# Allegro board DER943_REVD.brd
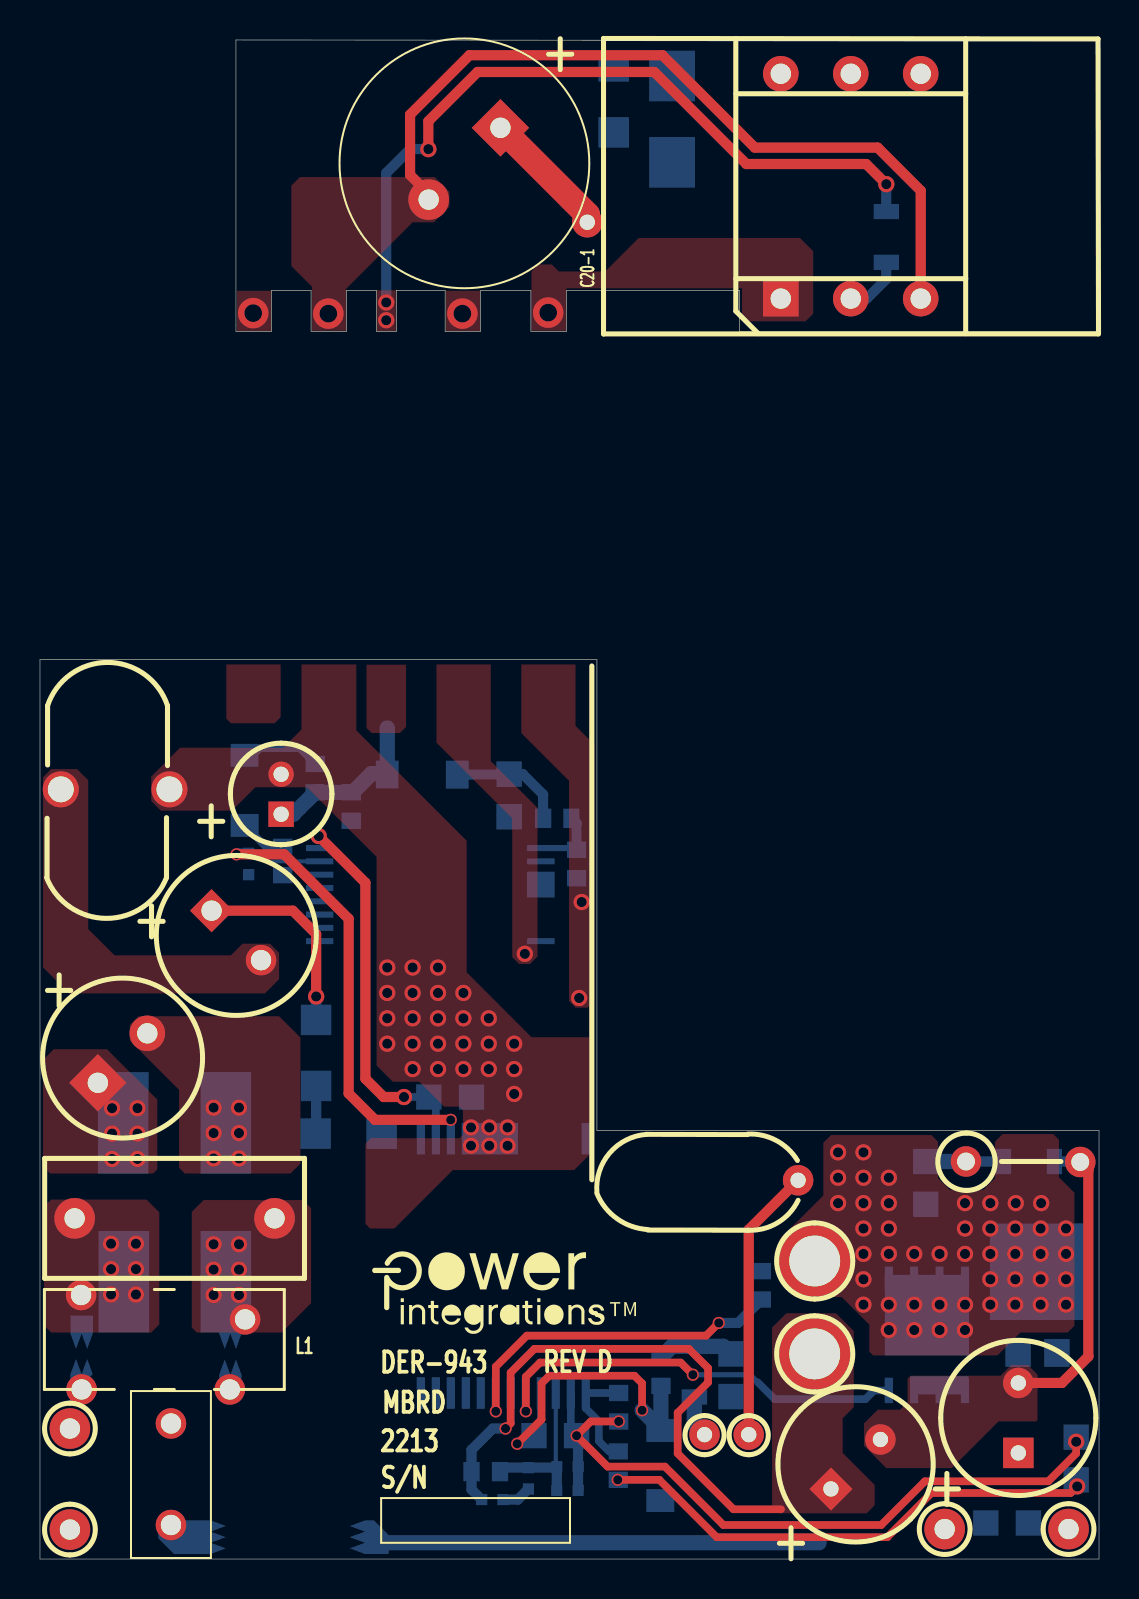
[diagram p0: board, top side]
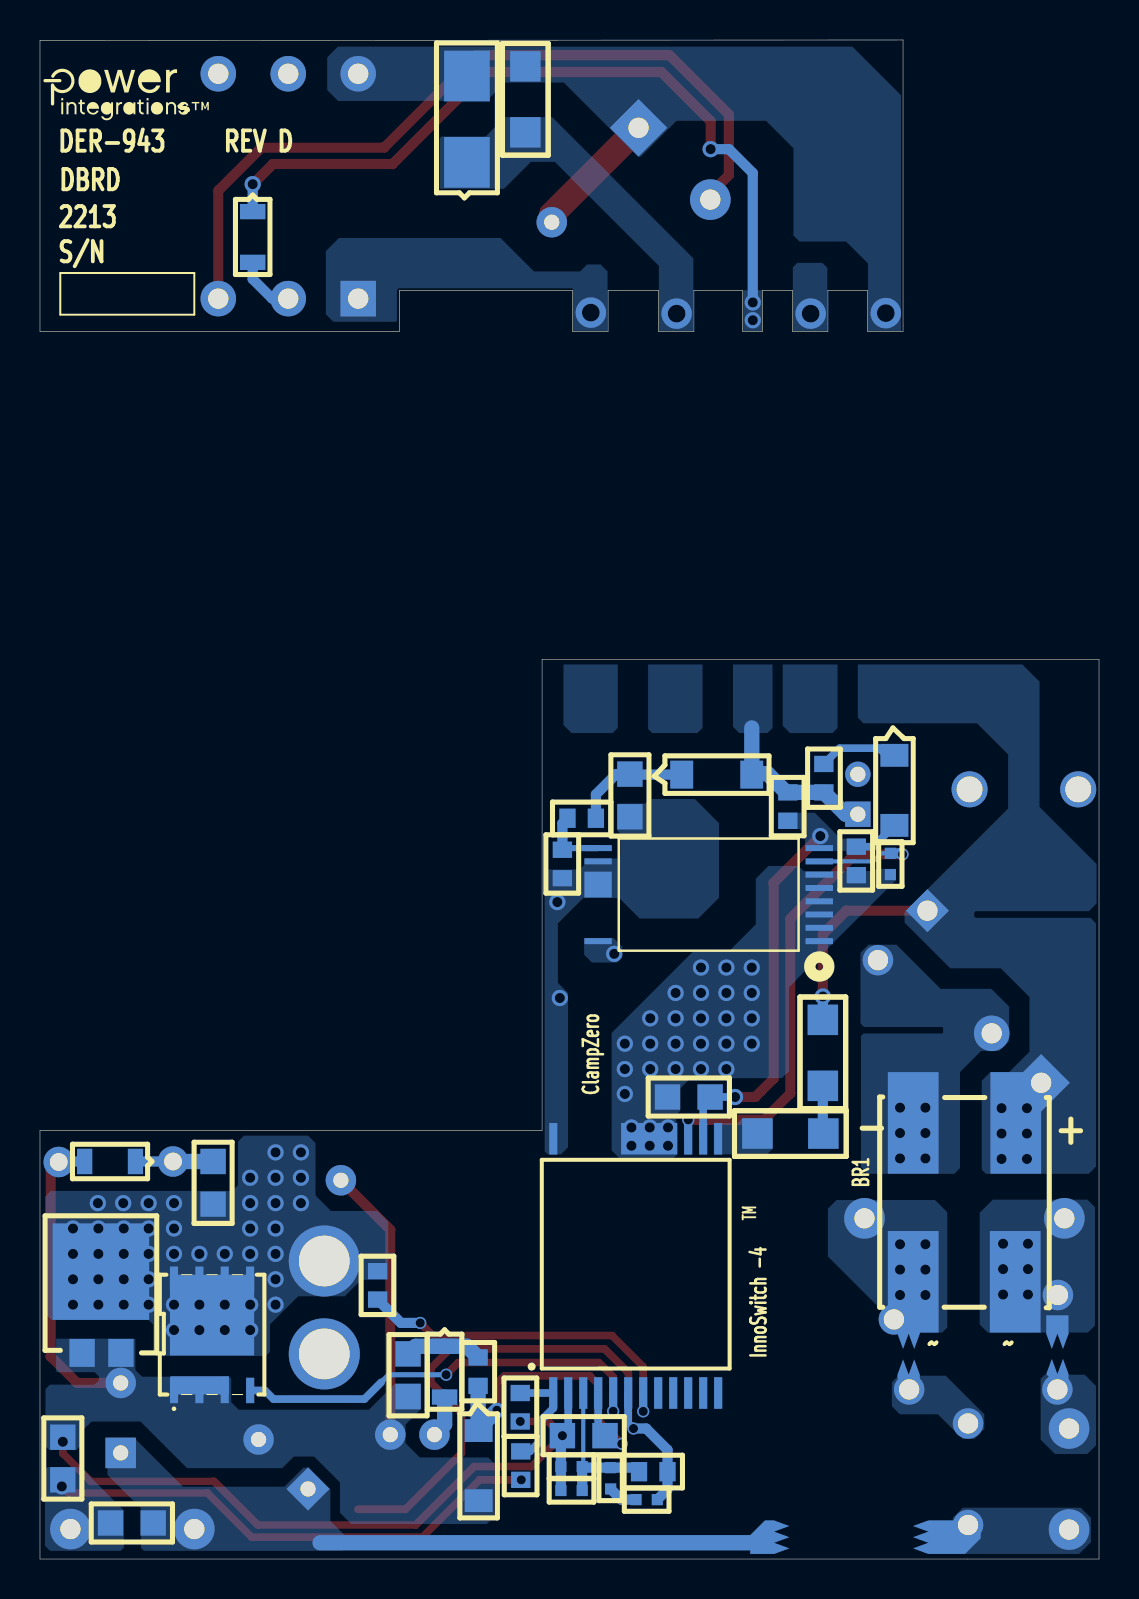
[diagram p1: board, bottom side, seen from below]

Outline 52.98 x 76 mm; copper layers: TOP, BOTTOM. Coordinates in mm from the lower left corner of the outline.
Outline path: 0,45.01 0,0 52.98,0 52.98,21.44 27.86,21.44 27.86,45.01 0,45.01 ; 9.8,76 9.8,61.42 11.58,61.42 11.58,63.47 13.56,63.47 13.56,61.42 15.34,61.42 15.34,63.47 16.84,63.47 16.84,61.42 17.83,61.42 17.83,63.47 20.27,63.47 20.27,61.42 22.05,61.42 22.05,63.47 24.56,63.47 24.56,61.42 26.34,61.42 26.34,63.47 35,63.47 35,61.42 52.98,61.42 52.98,75.97 9.86,76 9.8,76

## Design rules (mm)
constraint set DEFAULT: min track width 0.508

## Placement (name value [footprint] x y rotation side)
BR1  Z4DGP408L-HF  [PI_SM_D_Z4D]  4.19 21.87 180 bottom
C1  0.1 uF  [PINPXCAPRAD13X6X12P1MM040]  11.73 17.04 180 top
C2  10  uF  [PI_POLCAPD8MMXLLS3P5MM063V]  2.9 23.83 45 top
C3  10  uF  [PI_POLCAPD8MMXLLS3P5MM063V]  8.59 32.44 315 top
C4  100 uF  [PIPOLCAPCLYD500LS200040]  23.04 71.6 225 top
C5  100 nF  [PISMC1206]  28.7 74.68 270 bottom
C6  100 nF  [PISMC0603]  26.85 35.48 270 bottom
C7  1 uF  [PISMC0805]  23.47 37.13 90 bottom
C8  100 nF  [PISMC0603]  12.14 35.64 270 bottom
C9  22 uF  [PIPOLCAPCLYD200LS80030]  12.06 37.26 90 top
C10  0.47 uF  [PISMC0805]  19.46 23.11 0 bottom
C11  1 nF  [PISMC0805]  44.32 17.75 90 bottom
C12  330 uF  [PIPOLCAPCYLD315LS138D030]  39.57 3.51 45 top
C13  330 uF  [PIPOLCAPCYLD315LS138D030]  48.95 5.31 90 top
C14  330 pF  [PISMR0402]  24.43 3.51 90 bottom
C15  330 pF  [PISMR0402]  25.86 4.62 0 bottom
C16  1 uF  [PISMC0805]  47.32 1.8 0 bottom
C17  2.2 uF  [PISMC0805]  26.85 6.17 180 bottom
C18  10 uF  [PISMC0805]  34.57 10.26 270 bottom
C19  4.7 uF  [PISMC0603]  28.96 6.88 90 bottom
C20  470 pF  [PINPCAPRAD7P5X11P5LS7P5MM030]  30.43 18.95 0 top
D1  HS1KFL  [PI_SM_SOD-123_12]  20.88 39.24 180 bottom
D2  BAV19WS  [PISMSOD323]  42.34 67.41 270 bottom
D3  V12P10-M3/86A  [PI_SM_D_TO-277A]  48.92 10.31 180 bottom
D4  BAV19WS  [PISMSOD323]  48.21 19.89 0 bottom
D5  BAV19WS  [PISMSOD323]  32.74 10.64 270 bottom
F1  3.15 A  [PI_RST_MICROFUSE]  6.55 1.7 90 top
FL1  Hole_70mils  [PI_HOLE_70MIL]  38.76 10.24 0 top
FL2  Hole_70mils  [PI_HOLE_70MIL]  38.76 14.88 0 top
FL3  Hole_30mils  [PI_HOLE_30MIL]  33.25 6.22 0 top
FL4  Hole_30mils  [PI_HOLE_30MIL]  35.46 6.22 0 top
GND  BLK  [PITPKEYSTONE100X100]  51.46 1.5 0 top
L  BLK  [PITPKEYSTONE100X100]  1.5 1.47 0 top
L1  415 uH  [PI_TOROID_CMC4P_V_275UH]  7.72 8.48 180 top
L2  68 uH  [PI2P14DX6MMWD060]  0.3 38.51 0 top
N  WHT  [PITPKEYSTONE100X100]  1.5 6.53 0 top
NOREF  -  []  0 45.01 0 top
NOREF#2  -  []  0 0 0 top
NOREF#3  -  []  16.64 15.82 0 top
NOREF#4  -  []  35 61.42 0 top
NOREF#5  -  []  9.8 63.47 90 top
NOREF#6  -  []  9.8 76 0 top
NOREF#7  -  []  -144.21 54.23 0 top
NOREF#8  -  []  52.98 0 90 top
NOREF#9  -  []  0 0 90 top
NOREF#10  -  []  -222.02 -144.78 0 top
NOREF#11  -  []  52.98 61.42 90 top
NOREF#12  -  []  53.37 74.45 180 bottom
Q1  AON6220  [PISMPQFN5X6B]  46.28 8.43 180 bottom
R1  1.3 k  [PISMR0603]  26.59 37.06 180 bottom
R2  30 k  [PISMR0402]  10.44 35.31 270 bottom
R3  1.1 k  [PISMR0603]  15.57 38.35 270 bottom
R4  47  [PISMR0603]  13.77 38.35 90 bottom
R5  2.00 M  [PISMR1206]  13.82 26.97 270 bottom
R6  2.00 M  [PISMR1206]  13.79 21.29 0 bottom
R7  300  [PISMR0603]  36.09 14.4 270 bottom
R8  10  [PI12WVRESD180LS150D040]  46.33 19.89 0 top
R9  169 k  [PISMR0603]  21.59 4.37 0 bottom
R10  11.3 k  [PISMR0402]  25.86 3.43 0 bottom
R11  10 K  [PISMR0402]  22.1 2.97 0 bottom
R12  470  [PISMR0603]  31.06 8.66 90 bottom
R13  10  [PISMR0603]  28.93 5.38 270 bottom
R14  0.010  [PISMR0805]  51.84 6.1 270 bottom
T1  ATQ23.7/14  [PI_BOBBIN_ATQ23_7_H_6P]  40.56 68.68 90 top
U1  CPZ1075M  [PI_SM_MINSOP16A_1]  14 30.91 90 bottom
U2  INN4075C-H180  [PI_IC_INSOP_24D_IPC]  27.3 8.31 90 bottom
VOUT  RED  [PITPKEYSTONE100X100]  45.26 1.5 0 top
VR1  SMAJ170A-13-F  [PISMDO214AC12]  31.62 69.88 90 bottom
VR2  MMSZ5239B-7-F  [PI_SM_SOD-123_12]  10.24 40.21 270 bottom
VR3  DNP  [PI_SM_SOD-123_12]  31.04 6.43 270 bottom

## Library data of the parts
BR1 = DISCRETE BRIDGE_+~~-
C1 = CAP NP: alternate symbols: (pinpxcaprad13x6x12p1mm040H)
C2 C3 = CAP POL: alternate symbols: (PI_POLCAPD8mmxlLS3p5mm063V)
C4 = CAP POL: alternate symbols: (pipolcapclyd500ls2000401650lh)
C5-C8 C10 C16-C20 = CAP NP
C9 = CAP POL: alternate symbols: (pipolcapclyd200ls80030h)
C11 = CAP NP: alternate symbols: (pismc0805_1)
C12 C13 = CAP POL: alternate symbols: (pipolcapcyld315ls138d030h)
C14 C15 = CAP NP: alternate symbols: (pismr0402_1)
D1 D2 D4 D5 = DIODE
D3 = DIODE SCHOTTKY_TO-277A
F1 = FUSE: alternate symbols: (pirstmicrofusehoz)
FL1-FL4 = FlyingLead
GND L = TESTPOINT: alternate symbols: (TP_TH_CR2_D1_1)
L1 = TORRID 4P_12_34: alternate symbols: (pi_toroid_CMC4p_V,pi_toroid_CMC4p_V_275uH)
L2 = INDUCTOR
N VOUT = TESTPOINT
Q1 = FET_N_SGD_123_4_5678
R1-R3 R5-R7 R9-R14 = R
R4 = R: alternate symbols: (pismr0603_1)
R8 = R: alternate symbols: (pi12wvresd180ls200d040,pi12wvresd180ls250d040,pi12wresd180ls675d040)
T1 = BATQ23_7_6P/GENERIC
U1 = ClampZeroMinSOP16
U2 = MinnoPriSecCZ: alternate symbols: (pi_ic_insop_24d,PI_IC_INSOP24B)
VR1-VR3 = DIODE_ZENER

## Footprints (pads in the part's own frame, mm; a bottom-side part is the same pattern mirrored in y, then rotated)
PI2P14DX6MMWD060
  round 1.803 hole 1.295: 1(0.737,0) 2(6.172,0)
PI12WVRESD180LS150D040
  round 1.524 hole 0.889: 1(0,0) 2(5.715,-0.025)
PI_BOBBIN_ATQ23_7_H_6P
  rect 1.778x1.778 hole 1.016: 1(-5.625,3.5)
  round 1.778 hole 1.016: 2(-5.625,0) 3(-5.625,-3.5) 4(5.625,-3.5) 5(5.625,0) 6(5.625,3.5)
PI_HOLE_30MIL
  round 1.524 hole 0.762: 1(0,0)
PI_HOLE_70MIL
  round 3.556 hole 2.54: 1(0,0.025)
PI_IC_INSOP_24D_IPC
  rect 1.58x0.409 smd: 1(0,0) 2(0,-0.749) 3(0,-1.501) 4(0,-2.25) 5(0,-3) 6(0,-3.749) 7(0,-4.501) 8(0,-5.25) 9(0,-6) 10(0,-6.749) 11(0,-7.501) 12(0,-8.25) 13(12.72,-8.25) 14(12.72,-7.501) 15(12.72,-6.749) 24(12.72,0)
  rect 1.58x2.809 smd: 16(12.72,-4.801)
PI_POLCAPD8MMXLLS3P5MM063V
  rect 2.032x2.032 hole 1.016: 1(0,0)
  round 1.778 hole 1.016: 2(3.5,0)
PI_RST_MICROFUSE
  round 1.524 hole 1.016: 1(0,0) 2(5.08,0)
PI_SM_D_TO-277A
  rect 1.27x1.397 smd: 1(-0.015,0) 2(-1.956,0)
  rect 4.826x4.826 smd: 3(-1.016,4.064)
PI_SM_D_Z4D
  rect 2.54x5.08 smd: 1(0.025,-0.051) 2(0,-8.001) 3(-5.105,-8.001) 4(-5.105,-0.051)
PI_SM_MINSOP16A_1
  rect 0.3x1.369 smd: 1(0,0) 2(0.666,0) 3(1.331,0) 4(1.994,0) 5(2.659,0) 6(3.325,0) 7(3.99,0) 8(4.656,0) 9(4.656,11.067) 10(3.99,11.067) 16(0,11.067)
  rect 1.293x1.369 smd: 11(2.83,11.067)
PI_SM_SOD-123_12
  rect 1.143x1.397 smd: 1(0,0) 2(3.505,0)
PI_TOROID_CMC4P_V_275UH
  round 1.524 hole 1.016: 1(-1.778,0) 2(-2.54,-3.505) 3(5.639,0) 4(5.664,-4.724)
PINPCAPRAD7P5X11P5LS7P5MM030
  round 1.524 hole 0.762: 1(-3.048,47.93) 2(7.501,0)
PINPXCAPRAD13X6X12P1MM040
  round 2.032 hole 1.016: 1(0,0) 2(10,0)
PIPOLCAPCLYD200LS80030
  rect 1.27x1.27 hole 0.762: 1(0,0)
  round 1.27 hole 0.762: 2(1.999,0)
PIPOLCAPCLYD500LS200040
  rect 2.032x2.032 hole 1.016: 1(0,0)
  round 2.032 hole 1.016: 2(5.08,0)
PIPOLCAPCYLD315LS138D030
  rect 1.524x1.524 hole 0.762: 1(0,0)
  round 1.524 hole 0.762: 2(3.5,0)
PISMC0603
  rect 0.813x0.965 smd: 1(0,0) 2(1.422,0)
PISMC0805
  rect 1.27x1.27 smd: 1(0,0) 2(2.134,0)
PISMC1206
  rect 1.524x1.524 smd: 1(0,0) 2(3.302,0)
PISMDO214AC12
  rect 2.54x2.286 smd: 1(0,0) 2(4.318,0)
PISMPQFN5X6B
  rect 0.406x1.27 smd: 1(0,0) 2(1.27,0) 3(2.54,0) 4(3.81,0)
  rect 0.406x1.219 smd: 5(3.81,5.588) 6(2.54,5.588) 7(1.27,5.588) 8(0,5.588)
PISMR0402
  rect 0.559x0.559 smd: 1(0,0) 2(1.067,0)
PISMR0603
  rect 0.813x0.965 smd: 1(0,0) 2(1.422,0)
PISMR0805
  rect 1.27x1.27 smd: 1(0,0) 2(2.134,0)
PISMR1206
  rect 1.524x1.524 smd: 1(0,0) 2(3.302,0)
PISMSOD323
  rect 0.762x1.27 smd: 1(0,0) 2(2.54,0)
PITPKEYSTONE100X100
  round 2.032 hole 1.016: 1(0,0)

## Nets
N12670317: BR1.2 C1.2 L1.4
N12670400: BR1.3(AC2) C1.1 L1.2
N12670412: BR1.4 C2.2 C3.2 L2.1
N12670895: F1.2 L1.1
N12670899: L1.3 N.1
N12670957: F1.1 L.1
N12672041: BR1.1 C2.1 C3.1 C4.1 C5.1 C20.1 R5.1 T1.6 VR1.2
N12672408: C4.2 C8.2 C9.2 C10.2 L2.2 R2.2 T1.3 U1.1 U1.2 U1.3 U1.4 U1.5 U1.6 U2.16
N12673168: C5.2 U1.16 VR1.1
N12673753: C6.2 C7.1 T1.1 U1.10 U1.11 U2.24
N12673894: C7.2 D1.1 R1.2
N12673924: C6.1 R1.1 U1.9
N12674067: C8.1 C10.1 R3.2 U1.8 U2.14 VR2.2
N12674079: R2.1 U1.7 U2.15
N12675426: R4.2 VR2.1
N12675537: C9.1 D1.2 D2.1 R3.1 R4.1
N12675653: R6.2 U2.13
N12677294: D2.2 T1.2
N12679725: R5.2 R6.1
N12683607: R7.2 U2.7
N12683655: C12.1 C13.1 C16.1 FL1.1 R9.1 R11.1 U2.6 VOUT.1
N12683824: Q1.4 U2.5
N12683873: C11.1 D3.3(CATHODE) FL2.1 Q1.5 Q1.6 Q1.7 Q1.8 R7.1
N12684085: C12.2 C13.2 C15.2 C17.1 C18.2 C19.1 C20.2 D3.1 D3.2 D4.2 FL4.1 Q1.1 Q1.2 Q1.3(S3) R8.2 R10.2 R14.1 U2.2 VR3.2
N12684571: C11.2 D4.1 R8.1
N12685741: C14.2 C15.1 R9.2 R10.1 U2.3
N12685823: C14.1 R11.2
N12687150: C17.2 R12.1 U2.4 VR3.1
N12687458: C18.1 D5.1 R12.2
N12687556: D5.2 FL3.1
N12687728: C19.2 R13.1 U2.1
N12688309: C16.2 GND.1 R13.2 R14.2

Pads without a net: T1 4 5; U2 8 9 10 11 12

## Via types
v1: diameter 0.813, hole 0.508, TOP to BOTTOM, 112 vias
v2: diameter 0.61, hole 0.457, TOP to BOTTOM, 12 vias
v3: diameter 1.524, hole 0.889, TOP to BOTTOM, 4 vias

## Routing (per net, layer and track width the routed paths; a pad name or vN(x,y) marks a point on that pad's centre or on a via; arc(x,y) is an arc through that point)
N12670317:
  vias: v1(3.56,15.77) v1(3.56,14.5) v1(3.56,13.23) v1(4.8,15.77) v1(4.8,14.5) v1(4.8,13.23)
N12670400:
  vias: v1(8.69,15.75) v1(8.69,14.48) v1(8.69,13.21) v1(9.96,15.75) v1(9.96,14.48) v1(9.96,13.21)
N12670412:
  vias: v1(8.69,22.58) v1(8.69,21.31) v1(8.69,20.04) v1(9.96,22.58) v1(9.96,21.31) v1(9.96,20.04)
N12672041: length 16.5
  TOP w0.508: C3.1 12.65,32.44 13.82,31.27 v1(13.82,28.14)
  TOP w1.27: C4.1 27.38,67.26 C20.1
  BOTTOM w0.508: R5.1 v1(13.82,28.14)
  vias: v1(3.61,22.56) v1(3.61,21.29) v1(3.61,20.02) v1(4.88,22.56) v1(4.88,21.29) v1(4.88,20.02) v3(10.67,62.33)
N12672408: length 39.6
  TOP w0.508: T1.3 44.06,68.46 41.91,70.61 35.76,70.61 31.14,75.23 21.49,75.23 18.52,72.26 18.52,69.24 19.45,68.31 C4.2
  vias: v1(17.37,29.59) v1(17.37,28.32) v1(17.37,27.05) v1(17.37,25.78) v1(18.64,29.59) v1(18.64,28.32) v1(18.64,27.05) v1(18.64,25.78) v1(18.64,24.51) v1(19.91,29.59) v1(19.91,28.32) v1(19.91,27.05) v1(19.91,25.78) v1(19.91,24.51) v1(21.18,28.32) v1(21.18,27.05) v1(21.18,25.78) v1(21.18,24.51) v1(21.56,21.59) v1(21.56,20.68) v1(22.45,27.05) v1(22.45,25.78) v1(22.45,24.51) v1(22.48,21.59) v1(22.48,20.68) v1(23.39,21.59) v1(23.39,20.68) v1(23.72,25.78) v1(23.72,24.51) v1(23.72,23.27) v3(14.43,62.31)
N12673168:
  vias: v1(24.26,30.28) v3(21.13,62.31)
N12673753:
  vias: v1(26.97,28.07) v1(27.1,32.87) v3(25.43,62.36)
N12673894: length 5.9
  BOTTOM w0.508: D1.1 23.44,39.24 C7.2 24.16,39.27 25.17,38.25 R1.2
N12673924: length 3.5
  BOTTOM w0.305: C6.1 26.76,35.57 U1.9
  BOTTOM w0.508: R1.1 26.85,36.8 C6.1
N12674067: length 21.3
  TOP w0.508: v1(13.94,36.17) 16.28,33.83 16.28,24.03 17.2,23.11 v1(18.21,23.11)
  BOTTOM w0.254: C8.1 12.21,35.57
  BOTTOM w0.381: C8.1 11.3,35.64 10.24,36.7 ; v1(18.21,23.11) C10.1 19.8,22.77 U2.14
N12674079: length 26.6
  TOP w0.508: v2(20.55,21.97) 16.76,21.97 15.44,23.29 15.44,32.03 12.22,35.26 v2(9.83,35.26)
  BOTTOM w0.203: U1.7 11.3,34.9 10.9,35.31 R2.1
  BOTTOM w0.381: v2(20.55,21.97) 20.56,21.96 U2.15
  BOTTOM w0.508: v2(9.83,35.26) 9.88,35.31 R2.1
N12675426: length 4
  BOTTOM w0.381: R4.2 12.98,40.56 11,40.56 10.64,40.21 VR2.1
N12675537: length 46.6
  TOP w0.508: v1(42.34,68.78) 41.33,69.79 35.34,69.79 30.73,74.4 21.89,74.4 19.43,71.93 v1(19.43,70.54)
  BOTTOM w0.508: D2.1 v1(42.34,68.78) ; v1(17.32,62.87) 17.32,69.34 18.52,70.54 v1(19.43,70.54)
  BOTTOM w0.762: 17.37,41.58 D1.2 17.32,39.29 16.59,39.29 15.65,38.35 R3.1 R4.1 12.67,37.26 C9.1
  vias: v1(17.32,61.98)
N12677294: length 3
  BOTTOM w0.508: T1.2 41.36,63.06 42.34,64.03 D2.2
N12679725: length 2.4
  BOTTOM w0.508: R5.2 13.82,21.31 R6.1
N12683607: length 17.8
  TOP w0.381: v2(33.96,11.81) 33.32,11.18 24.36,11.18 22.8,9.62 v2(22.8,7.39)
  BOTTOM w0.381: U2.7 v2(22.8,7.39)
  BOTTOM w0.508: v2(33.96,11.81) 34.92,11.81 R7.2
N12683655: length 53.9
  TOP w0.381: v2(23.29,6.53) 23.55,6.78 23.55,9.32 24.74,10.52 32.46,10.52 33.43,9.55 33.43,8.84 31.9,7.32 31.9,5.28 34.7,2.49 37.08,2.49
  BOTTOM w0.381: v2(23.29,6.53) 23.56,6.79 U2.6
  BOTTOM w0.508: v2(23.29,6.53) 22.66,6.53 21.59,5.46 R9.1 21.59,3.48 R11.1
  BOTTOM w0.762: 38.97,0.81 16.66,0.81
N12683824: length 22
  TOP w0.381: v2(32.66,9.22) 32.05,9.83 25.02,9.83 24.31,9.12 v2(24.31,7.39)
  BOTTOM w0.254: 35.92,8.84 35.53,9.22 v2(32.66,9.22)
  BOTTOM w0.381: 35.92,8.84 36.75,8 41.3,8 41.73,8.43 Q1.4 ; U2.5 24.31,7.39 v2(24.31,7.39)
N12683873:
  vias: v1(39.93,20.35) v1(39.93,19.08) v1(39.93,17.81) v1(41.2,20.35) v1(41.2,19.08) v1(41.2,17.81) v1(41.2,16.54) v1(41.2,15.27) v1(41.2,14) v1(41.2,12.73) v1(42.47,19.08) v1(42.47,17.81) v1(42.47,16.54) v1(42.47,15.27) v1(42.47,12.73) v1(42.47,11.46) v1(43.74,15.27) v1(43.74,12.73) v1(43.74,11.46) v1(45.01,15.27) v1(45.01,12.73) v1(45.01,11.46) v1(46.28,17.81) v1(46.28,16.54) v1(46.28,15.27) v1(46.28,12.73) v1(46.28,11.46) v1(47.55,17.81) v1(47.55,16.54) v1(47.55,15.27) v1(47.55,14) v1(47.55,12.73) v1(48.82,17.81) v1(48.79,16.54) v1(48.79,15.27) v1(48.79,14) v1(48.79,12.73) v1(50.09,17.81) v1(50.06,16.54) v1(50.06,15.27) v1(50.06,14) v1(50.06,12.73) v1(51.33,16.54) v1(51.33,15.27) v1(51.33,14) v1(51.33,12.73)
N12684085: length 65.4
  TOP w0.381: v1(51.84,5.87) 51.84,5.28 50.44,3.89 44.27,3.89 42.09,1.7 34.19,1.7 31.27,4.62 28.4,4.62 v2(26.85,6.17) 27.56,6.88 v2(28.96,6.88)
  TOP w0.508: R8.2 52.45,19.46 52.45,10.13 51.13,8.81 C13.2 ; FL4.1 35.46,16.48 C20.2
  BOTTOM w0.381: U2.2 26.56,6.46 v2(26.85,6.17)
  BOTTOM w0.508: R10.2 C15.2 26.92,6.1 v2(26.85,6.17) ; D4.2 52.02,19.89 R8.2
N12684571: length 3.9
  BOTTOM w0.508: D4.1 R8.1
  BOTTOM w0.762: C11.2 R8.1
N12685741: length 7.8
  BOTTOM w0.203: U2.3 25.8,4.68 C15.1
  BOTTOM w0.508: R9.2 23.22,4.57 C14.2 25.81,4.57 C15.1 R10.1
N12685823: length 1.5
  BOTTOM w0.508: R11.2 23.9,2.97 C14.1
N12687150: length 17.2
  TOP w0.381: v2(23.88,5.77) 25.1,6.99 25.1,8.79 25.48,9.17 29.74,9.17 30.12,8.79 v2(30.12,7.44)
  BOTTOM w0.381: v2(23.88,5.77) 24.31,5.77 C17.2 25.05,6.51 U2.4
  BOTTOM w0.762: 31.06,6.55 31.04,6.53 ; 31.06,6.55 31.06,6.45 VR3.1 31.04,6.53 ; 31.06,6.55 R12.1 ; 31.04,6.53 v2(30.12,7.44)
N12687458: length 3.9
  BOTTOM w0.762: R12.2 31.62,10.64 D5.1 34.19,10.64 C18.1
N12687556: length 2.1
  BOTTOM w0.762: D5.2 32.74,6.73 FL3.1
N12687728: length 5.5
  BOTTOM w0.381: R13.1 28.47,5.38 27.97,5.89 27.97,6.88 27.3,7.54 U2.1 C19.2
N12688309: length 25.2
  TOP w0.381: v1(51.89,3.63) 51.56,3.3 44.6,3.3 42.39,1.09 33.86,1.09 30.99,3.96 v2(28.91,3.96)

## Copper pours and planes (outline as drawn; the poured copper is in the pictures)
N12670317 on BOTTOM (solid shape): 2.64,11.28 2.36,10.52 2.08,11.28 1.8,10.52 1.52,11.28 1.52,12.19 2.64,12.19
N12670317 on TOP: 0.2,17.63 0.56,17.98 5.33,17.98 5.97,17.35 5.97,11.73 5.56,11.33 0.56,11.33 0.2,11.68
N12670317 on BOTTOM: 5.97,11.73 5.97,17.32 5.31,17.98 0.58,17.98 0.2,17.6 0.2,11.68 0.56,11.33 5.56,11.33
N12670400 on BOTTOM (solid shape): 9.77,12.18 9.77,11.6 10.08,11.28 9.8,10.52 9.53,11.28 9.25,10.52 8.97,11.28 8.97,12.19 9.75,12.19
N12670400 on TOP: 13.56,17.55 13.56,12.8 12.09,11.33 7.85,11.33 7.59,11.58 7.59,17.37 8.18,17.96 13.16,17.96
N12670400 on BOTTOM: 7.59,11.58 7.59,17.35 8.2,17.96 13.13,17.96 13.56,17.53 13.56,15.14 10.57,12.14 10.57,11.38 10.52,11.33 7.85,11.33
N12670412 on TOP: 3.73,30.2 2.41,31.52 2.41,38.96 1.85,39.52 0.56,39.52 0.15,39.12 0.15,29.59 1.45,28.3 11.25,28.3 11.96,29.01 11.96,30.33 11.51,30.78 10.13,30.78 9.55,30.2
N12670412 on TOP: 13.03,26.09 11.96,27.15 4.93,27.15 4.48,26.71 4.5,26.7 4.5,25.93 6.96,23.47 6.96,19.57 7.24,19.29 12.53,19.29 13.03,19.78
N12670412 on BOTTOM: 11.94,26.77 11.91,26.77 11.76,26.62 7.85,26.62 7.8,26.57 7.8,26.34 7.85,26.29 11.79,26.29 11.91,26.16 11.91,19.61 11.58,19.28 7.24,19.28 6.96,19.56 6.96,24.36 5.89,25.43 4.98,25.43 4.5,25.91 4.5,27.64 5.38,28.52 7.92,28.52 10.13,30.73 11.53,30.73 11.94,30.33
N12670895 on BOTTOM (solid shape): 10.08,9.22 10.08,9.04 9.35,8.31 8.97,8.31 8.97,9.22 9.25,9.98 9.53,9.22 9.8,9.98
N12670895 on BOTTOM: 6.82,6.01 8.05,7.24 9.96,7.24 10.36,7.65 10.36,8.84 10.03,9.17 7.67,9.17 5.74,7.24 5.74,6.5 6.24,6.01
N12670899 on BOTTOM (solid shape): 2.64,9.25 1.88,8.48 1.52,8.48 1.52,9.25 1.8,10.01 2.08,9.25 2.36,10.01
N12670899 on BOTTOM: 0.58,5.26 2.21,5.26 2.92,5.97 2.92,9.02 2.72,9.22 0.71,9.22 0.15,8.66 0.15,5.69
N12670957 on BOTTOM (solid shape): 9.3,1.65 8.53,1.37 9.3,1.09 8.53,0.81 9.3,0.53 8.53,0.25 6.71,0.25 5.92,1.04 5.92,1.93 8.53,1.93
N12670957 on BOTTOM: 0.91,2.57 6.81,2.57 7.32,2.06 7.32,0.66 6.91,0.25 0.99,0.25 0.41,0.84 0.41,2.06
N12672041 on TOP: 9.55,41.81 11.73,41.81 12.04,42.11 12.04,44.75 9.32,44.75 9.32,42.04
N12672041 on TOP: 5.87,19.49 5.66,19.28 0.51,19.28 0.15,19.63 0.15,19.86 0.15,24.97 0.69,25.5 3.36,25.5 5.87,22.99
N12672041 on TOP: 9.86,63.45 11.56,63.45 11.56,61.44 9.86,61.44
N12672041 on BOTTOM: 6.17,32.08 6.25,32.16 6.25,32.33 6.17,32.41 0.51,32.41 0.13,32.79 0.13,34.77 2.97,37.62 2.97,43.89 3.84,44.75 12.06,44.75 12.06,42.09 11.79,41.81 6.1,41.81 4.55,40.26 4.55,37.54 9.73,32.36 9.73,31.84 7.44,29.55 4.91,29.55 3.48,28.12 3.48,25.37 4.5,24.36 5.44,24.36 5.87,23.93 5.87,19.48 5.66,19.28 0.51,19.28 0.15,19.63 0.15,31.8 0.43,32.08
N12672041 on BOTTOM: 11.56,61.44 11.56,64.82 12.65,65.91 14.99,65.91 15.29,66.22 15.29,70.59 16.66,71.96 21.13,71.96 22.94,70.15 23.06,70.15 26.77,73.86 29.72,73.86 30.63,72.95 38.07,72.95 38.61,73.48 38.61,75.13 38.07,75.67 12.34,75.67 9.91,73.23 9.91,61.44
N12672408 on TOP: 19.75,69.14 13,69.14 12.57,68.71 12.57,64.69 13.61,63.65 13.61,61.44 15.32,61.44 15.32,63.55 18.64,66.88 19.71,66.88 20.49,67.65 20.49,68.4
N12672408 on TOP: 15.82,41.45 21.35,35.93 21.35,29.35 24.59,26.11 27.43,26.11 27.66,25.88 27.66,20.4 26.72,19.46 20.65,19.46 17.73,16.54 16.51,16.54 16.28,16.76 16.28,20.78 16.56,21.06 21.01,21.06 21.16,21.21 21.16,22.45 20.98,22.63 20.22,22.63 18.97,23.88 17.65,23.88 16.84,24.69 16.84,35.13 13.36,38.61 10.77,38.61 9.6,37.44 6.05,37.44 5.56,37.92 5.56,39.14 7.01,40.59 12.17,40.59 13.08,41.5 13.08,44.73 13.11,44.75 15.82,44.75
N12672408 on BOTTOM: 15.82,44.75 15.82,41.68 15.47,41.33 13.34,41.33 13.08,41.58 13.08,44.75
N12672408 on BOTTOM: 18.52,30.4 17.17,31.75 17.17,34.04 16.54,34.67 15.04,34.67 14.78,34.42 11.28,34.42 11.16,34.53 10.16,34.53 10.16,33.96 15.52,28.6 15.52,24.41 15.88,24.05 20.45,24.05 20.95,23.55 20.95,22.28 21.11,22.12 21.11,20.24 21.29,20.07 24,20.07 24.38,20.45 24.38,26.32 20.3,30.4
N12672408 on BOTTOM: 15.32,61.44 13.59,61.44 13.59,64.59 13.84,64.85 15.09,64.85 15.32,64.62
N12673168 on TOP: 20.29,63.45 22.02,63.45 22.02,61.44 20.29,61.44
N12673168 on TOP: 22.56,44.75 22.56,39.91 24.89,37.57 24.89,30.14 24.52,29.77 23.97,29.77 23.62,30.12 23.62,37.06 19.84,40.84 19.84,44.75
N12673168 on BOTTOM: 22.56,44.75 22.56,41.53 22.35,41.33 20.09,41.33 19.84,41.58 19.84,44.75
N12673168 on BOTTOM: 27.36,72.14 29.72,72.14 30.68,71.17 32.89,71.17 32.99,71.07 32.99,68.58 32.97,68.55 29.77,68.55 28.42,69.9 27.23,69.9 22.02,64.69 22.02,61.44 20.29,61.44 20.29,65.07
N12673168 on BOTTOM: 24.28,31.06 25.76,31.06 25.76,30.23 25.37,29.84 24.1,29.84 23.85,30.1 23.85,30.63
N12673753 on TOP: 24.08,44.75 26.8,44.75 26.8,41.68 27.74,40.74 27.74,28.03 27.74,27.92 27.4,27.58 26.8,27.58 26.47,27.91 26.47,38.94 24.08,41.33
N12673753 on TOP: 29.95,66.09 28.27,64.41 25.96,64.41 25.6,64.77 24.94,64.77 24.59,64.41 24.59,61.44 26.31,61.44 26.31,63.53 26.37,63.58 35.13,63.58 35.13,61.95 35.15,61.93 38.3,61.93 38.68,62.31 38.68,65.43 38.02,66.09
N12673753 on BOTTOM: 24.08,44.75 26.8,44.75 26.8,41.73 26.39,41.33 24.33,41.33 24.08,41.58
N12673753 on BOTTOM: 29.95,66.09 28.27,64.41 25.96,64.41 25.6,64.77 24.94,64.77 24.59,64.41 24.59,61.44 26.31,61.44 26.31,63.53 26.37,63.58 35.03,63.58 35.13,63.47 35.13,61.95 35.18,61.9 38.3,61.9 38.68,62.28 38.68,65.43 38.02,66.09
N12673753 on BOTTOM: 20.22,38.02 22.43,38.02 22.66,37.8 24.05,37.8 24.1,37.74 24.1,36.45 23.95,36.3 23.95,35.2 24.1,35.05 25.7,35.05 25.73,35.03 25.73,34.75 25.98,34.49 27.56,34.49 27.74,34.32 27.74,20.4 27.58,20.24 26.92,20.24 26.57,20.6 26.57,28.32 27.08,28.83 27.08,31.8 25.81,33.07 24,33.07 22.97,32.04 20.05,32.04 19.01,33.08 19.01,36.82
N12674067 on BOTTOM: 12.7,35.43 12.6,35.33 11.66,35.33 11.66,36.04 12.93,36.04 14.22,37.34 16.03,37.34 16.05,37.31 16.05,36.53 14.99,36.53 14.71,36.25 14.71,35.46 14.68,35.43
N12675537 on TOP: 16.34,44.72 16.36,44.74 18.31,44.74 18.31,41.63 18.01,41.33 16.59,41.33 16.34,41.58
N12675537 on TOP, BOTTOM: 16.87,63.47 17.81,63.47 17.81,61.44 16.87,61.44
N12675537 on BOTTOM: 16.33,44.75 18.31,44.75 18.31,41.64 18,41.33 16.59,41.33 16.33,41.58
N12675653 on BOTTOM: 19.2,21.79 18.08,21.79 17.83,22.05 16.31,22.05 16.31,20.55 16.61,20.24 19.28,20.24 19.28,21.72
N12683655 on BOTTOM (solid shape): 17.45,1.19 17.45,0.25 16.26,0.25 15.49,0.53 16.26,0.81 15.49,1.09 16.26,1.37 15.49,1.65 16.26,1.93 16.71,1.93
N12683655 on TOP: 36.63,2.67 37.01,2.29 41.35,2.29 41.76,2.69 41.76,3.71 40.16,5.31 40.16,7.04 40.72,7.59 40.72,11.4 39.83,12.29 37.34,12.29 36.63,11.58
N12683655 on BOTTOM: 49.61,4.22 47.93,2.54 47.93,0.56 47.78,0.41 37.86,0.41 37.72,0.55 37.72,1.18 37.73,1.18 38.46,1.91 38.46,3.48 39.55,4.57 39.8,4.57 40.75,3.62 45.83,3.62 48.29,6.07 49.61,6.07
N12683873 on BOTTOM (solid shape): 46.48,10.19 42.27,10.19 42.27,14.22 46.48,14.22
N12683873 on TOP: 44.6,21.21 44.93,20.88 44.93,19.05 45.5,18.48 47.21,18.48 47.78,19.05 47.78,20.88 48.16,21.26 50.7,21.26 50.98,20.98 50.98,19.1 51.75,18.33 51.75,11.67 51.41,11.33 49.05,11.33 47.9,10.19 44.07,10.19 41.68,10.19 41.49,10.38 41.49,11.72 40.11,13.11 37.77,13.11 37.01,13.87 37.01,16 39.19,18.19 39.19,20.83 39.57,21.21
N12683873 on BOTTOM: 42.77,21.18 43.08,20.88 43.08,18.69 43.36,18.41 52.43,18.41 52.7,18.14 52.7,12.27 52.4,11.96 47.55,11.96 47.32,11.73 47.32,10.41 47.07,10.16 41.68,10.16 41.48,10.36 41.48,11.73 40.07,13.14 37.73,13.14 36.91,13.97 35.61,13.97 35.56,14.02 35.56,16.87 36.11,17.41 38.42,17.41 39.19,18.19 39.19,20.8 39.57,21.18
N12684085 on BOTTOM (solid shape): 46.46,8.23 43.54,8.23 43.54,9.14 46.46,9.14
N12684085 on TOP: 48.06,9.17 48.59,9.7 49.43,9.7 49.91,9.22 49.91,6.96 49.83,6.88 47.96,6.88 45.62,4.55 42.34,4.55 41.22,5.66 41.22,6.78 41.91,7.47 43.03,7.47 43.41,7.85 43.41,9.02 43.56,9.17
N12684085 on BOTTOM: 52.17,11.02 52.17,9.4 52.12,9.35 50.24,9.35 50.04,9.14 50.04,8.94 50.25,8.72 52.48,8.72 52.7,8.5 52.7,5.64 52.53,5.46 51.16,5.46 50.95,5.66 50.95,6.32 50.39,6.88 47.96,6.88 45.62,4.55 40.87,4.55 40.28,5.13 39.27,5.13 37.97,3.84 37.97,2.31 37.41,1.75 30.63,1.75 30.25,2.13 30.25,4.78 30.56,5.08 33.99,5.08 34.7,5.79 34.7,6.73 33.93,7.49 33.93,8.79 35.2,8.79 36.53,7.47 43.04,7.47 43.42,7.85 43.42,9.03 43.54,9.14 43.81,9.14 43.84,9.12 47.88,9.12 48.21,9.45 48.21,10.97 48.26,11.02
N12688309 on BOTTOM: 52.73,0.66 52.48,0.41 48.95,0.41 48.79,0.56 48.79,2.44 50.95,4.6 52.6,4.6 52.73,4.47

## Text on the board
Ref Des/Silkscreen Bottom: TM | InnoSwitch -4 | ClampZero | REV D | DBRD | DER-943 | 2213 | S/N
Ref Des/Silkscreen Top: C20-1 | DER-943 | 2213 | S/N | MBRD | REV D | +
User.5: 14. FAB HOUSE LOGO,DATE CODE TO BE IN SILK SCREEN ONLY.DO NOT USE COPPER. | 13. MATERIAL FR4 COPPER 2oz THICKNESS 0.040" | PLATED SLOTS
User.8: FIGURE | FINISHED_SIZE | 18.0 | 20.0 | 30.0 | 35.0 | 40.0 | 51.0 | 100.0 | DRILL CHART: TOP to BOTTOM | ALL UNITS ARE IN MILS | TOLERANCE_DRILL | +3.0/-3.0 | PLATED | QTY | 12 | 112 | 10 | 6 | 24 | 2
